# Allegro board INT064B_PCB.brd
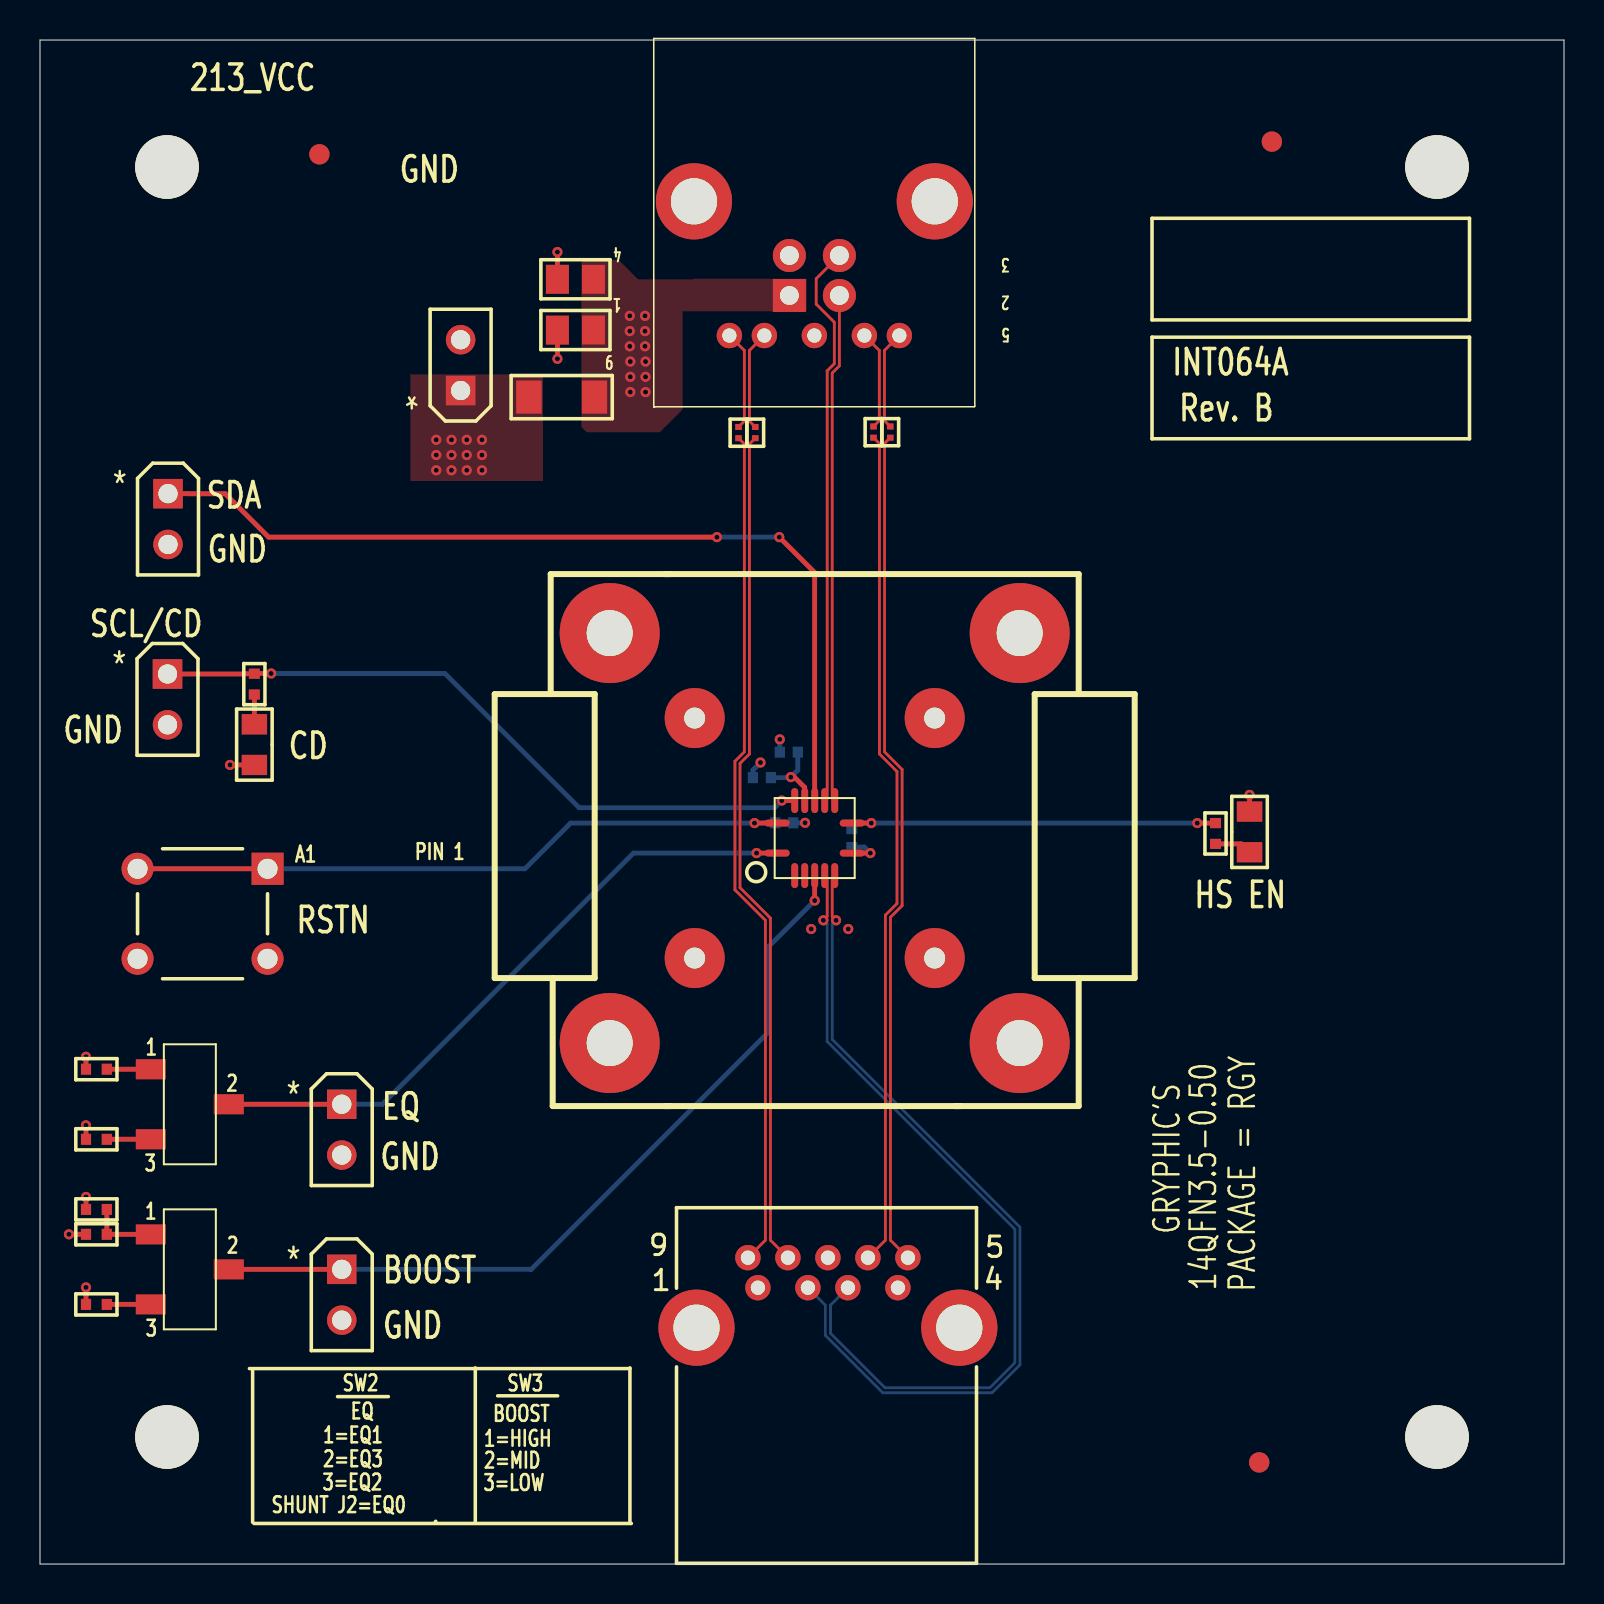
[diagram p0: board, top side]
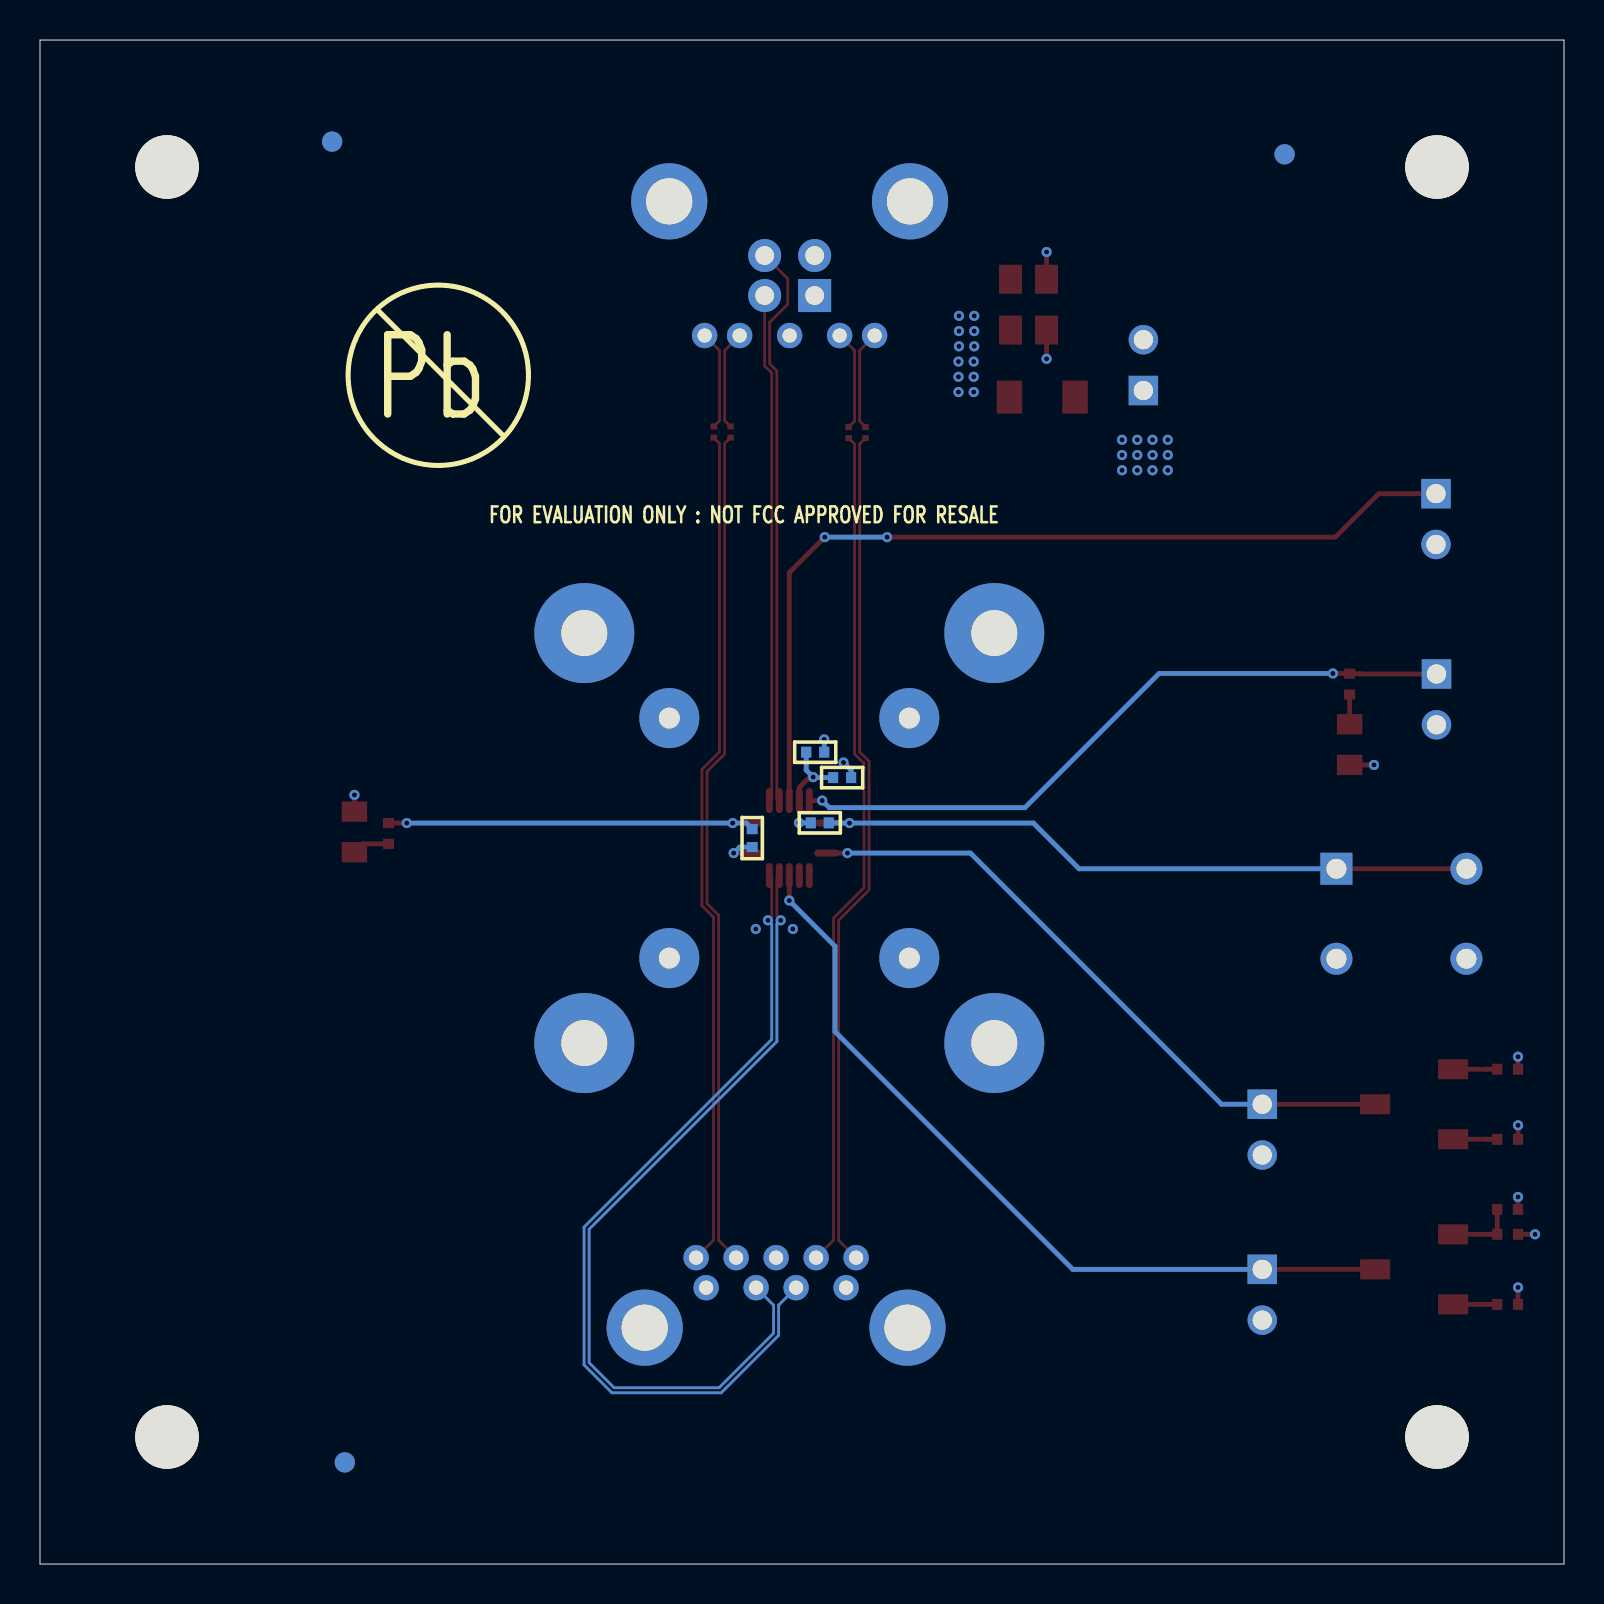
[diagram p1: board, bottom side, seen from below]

Outline 76.2 x 76.2 mm; copper layers: TOP, L2_GND, L3_PWR, BOTTOM. Coordinates in mm from the lower left corner of the outline.
Outline path: 0,76.2 76.2,76.2 76.2,0 0,0 0,76.2

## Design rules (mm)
net group DIFFPAIR0: nets D1M D1P
net group DIFFPAIR1: nets D2M D2P
net group DIFFPAIR2: nets N00734 N00738
net group DIFFPAIR3: nets SS_RXN SS_RXP
net group DIFFPAIR4: nets N00742 N00746
net group DIFFPAIR5: nets SS_TXN SS_TXP

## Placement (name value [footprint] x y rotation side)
C1  0.1uF  [C0402]  40.59 36.3 270 bottom
C2  0.1uF  [C0402]  37.21 37.06 0 bottom
C3  10uF  [C0805]  26.77 64.24 180 top
C4  1uF  [C0805]  26.77 61.7 180 top
C5  1uF  [C0402]  37.44 40.59 180 bottom
C6  0.1uF  [C0402]  36.09 39.32 180 bottom
D1  LED  [0805]  10.72 40.97 90 top
D2  LED  [0805]  60.48 36.6 270 top
J1  HDR2X1 M .1  [HDR_THVT_1X2_100]  21.03 58.67 180 top
J2  HDR2X1 M .1  [HDR_THVT_1X2_100]  15.09 22.99 0 top
J3  HDR2X1 M .1  [HDR_THVT_1X2_100]  6.4 53.52 0 top
J4  HDR2X1 M .1  [HDR_THVT_1X2_100]  6.38 44.5 0 top
J5  HDR2X1 M .1  [HDR_THVT_1X2_100]  15.09 14.73 0 top
NOREF  -  []  -3.81 -69.85 0 top
NOREF#2  -  []  0 76.2 0 top
NOREF#3  -  []  76.2 0 90 top
NOREF#4  -  [unnamed#2]  6.35 69.85 0 top
NOREF#5  -  []  73.51 21.26 90 top
NOREF#6  -  [unnamed#2]  13.97 70.48 0 top
NOREF#7  -  [unnamed#2]  61.59 71.12 0 top
NOREF#8  -  [unnamed#2]  60.96 5.08 0 top
NOREF#9  -  [unnamed#2]  6.35 6.35 0 top
NOREF#10  -  []  88.9 38.1 0 top
NOREF#11  -  [unnamed#2]  69.85 69.85 0 top
NOREF#12  -  [unnamed#2]  69.85 6.35 0 top
NOREF#13  -  []  0 0 0 top
NOREF#14  -  []  10.39 60.66 180 bottom
NOREF#15  -  [unnamed#2]  61.59 71.12 180 bottom
NOREF#16  -  []  56.29 59.44 180 bottom
NOREF#17  -  [unnamed#2]  60.96 5.08 180 bottom
NOREF#18  -  [unnamed#2]  13.97 70.48 180 bottom
P1  USB3.0 Type B Receptacle  [USB3_TYPEB_AK4AA009]  37.47 63.42 180 top
P2  USB3 Type A Receptacle  [USB3_TYPEA]  39.4 15.32 0 top
R1  0  [R0201]  34.92 56.57 270 top
R2  0  [R0201]  35.76 56.57 270 top
R3  0  [R0201]  41.68 56.59 270 top
R4  0  [R0201]  42.51 56.59 270 top
R5  0  [R1206]  26.09 58.34 180 top
R6  1.7K  [R0402]  2.82 24.74 0 top
R7  3.8K  [R0402]  2.82 21.23 0 top
R8  75  [R0402]  10.72 43.99 90 top
R9  75  [R0402]  58.78 36.53 270 top
R10  15K  [R0402]  2.82 16.48 0 top
R11  12K  [R0402]  2.82 12.98 0 top
R12  30K  [R0402]  2.82 17.73 0 top
SW1  Switch - Push Button  [SW_THVT_EVQPAX04]  8.13 32.51 270 top
SW2  Switch CJS-1201  [CJS-1200B]  7.49 22.99 0 top
SW3  Switch CJS-1201  [CJS-1200B]  7.49 14.73 0 top
U1  TUSB213  [RGY_NOPOWERPAD_SOCKET]  38.73 36.3 0 top

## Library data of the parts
C1 C2 C5 C6 = cc0402
C3 C4 = cc0805
D1 D2 = d0805 Green
J1-J5 = HDR2X1 M .1
P1 = USB 3.0 Type B Receptacle
P2 = USB 3.0 Type A Receptacle
R1-R4 = r0201
R5 = r1206
R6-R12 = r0402
SW1 = Switch - Push Button_0
SW2 SW3 = Switch CJS-1201
U1 = TUSB213RGY_2

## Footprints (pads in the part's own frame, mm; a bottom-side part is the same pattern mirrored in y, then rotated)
0805
  rect 1.016x1.27 smd: 1(-1.016,0) 2(1.016,0)
C0402
  rect 0.51x0.55 smd: 1(-0.45,0) 2(0.45,0)
C0805
  rect 1.15x1.45 smd: 1(-0.9,0) 2(0.9,0)
CJS-1200B
  rect 1.5x1 smd: 1(-1.95,1.75) 2(1.95,0) 3(-1.95,-1.75)
HDR_THVT_1X2_100
  rect 1.473x1.473 hole 0.965: 1(0,0)
  round 1.473 hole 0.965: 2(0,-2.54)
R0201
  rect 0.3x0.33 smd: 1(-0.285,0) 2(0.275,0)
R0402
  rect 0.51x0.55 smd: 1(-0.52,0) 2(0.52,0)
R1206
  rect 1.27x1.65 smd: 1(-1.64,0) 2(1.64,0)
RGY_NOPOWERPAD_SOCKET
  round 5 hole 2.3: (-10.25,10.25) (-10.25,-10.25) (10.25,10.25) (10.25,-10.25)
  round 3 hole 1.05 unplated: (-6,6) (-6,-6) (6,6) (6,-6)
  oval 1.25x0.35 smd: 1(-1.875,-0.75) 7(1.875,-0.75) 8(1.875,0.75) 14(-1.875,0.75)
  oval 0.35x1.25 smd: 2(-1,-1.875) 3(-0.5,-1.875) 4(0,-1.875) 5(0.5,-1.875) 6(1,-1.875) 9(1,1.875) 10(0.5,1.875) 11(0,1.875) 12(-0.5,1.875) 13(-1,1.875)
SW_THVT_EVQPAX04
  rect 1.6x1.6 hole 1: A1(-2.25,3.25)
  round 1.6 hole 1: A2(-2.25,-3.25) B1(2.25,3.25) B2(2.25,-3.25)
unnamed#2
  round 3.175 hole 3.175 unplated: (0,0)
USB3_TYPEA
  round 1.27 hole 0.711: 1(-3.5,-1.5) 2(-1,-1.5) 3(1,-1.5) 4(3.5,-1.5) 5(4,0) 6(2,0) 7(0,0) 8(-2,0) 9(-4,0)
  round 3.81 hole 2.311: 10(-6.57,-3.5) 11(6.57,-3.5)
USB3_TYPEB_AK4AA009
  rect 1.651x1.651 hole 0.94: 1(0,0)
  round 1.651 hole 0.94: 2(-2.5,0) 3(-2.5,-2) 4(0,-2)
  round 1.27 hole 0.711: 5(-5.5,2) 6(-3.75,2) 7(-1.25,2) 8(1.25,2) 9(3,2)
  round 3.81 hole 2.311: 10(-7.27,-4.71) 11(4.77,-4.71)

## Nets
GND: C1.2 C2.2 C3.2 C4.2 C5.2 C6.2 D1.1 D2.1 J1.2 J2.2 J3.2 J4.2 J5.2 P1.4(GND) P1.7(GND_DRAIN) P1.10(SHIELD1) P1.11(SHIELD2) P2.4(GND) P2.7(GND_DRAIN) P2.10(SHIELD1) P2.11(SHIELD2) R6.1 R7.1 R11.1 R12.1 SW1.B1 SW1.B2 U1.7(GND)
VBUS: C3.1 C4.1 P1.1(VBUS) P2.1(VBUS) R5.1
213_VCC: C5.1 C6.1 J1.1 R5.2 R10.1 U1.12(VCC)
BOOST: J5.1 SW3.2 U1.4(BOOST/ENA_HS)
D1M: P1.2(USB2_DM) U1.9(D1M)
D1P: P1.3(USB2_DP) U1.10(D1P)
D2M: P2.2(USB2_DM) U1.6(D2M)
D2P: P2.3(USB2_DP) U1.5(D2P)
EQ: J2.1 SW2.2 U1.1(EQ)
RSTN: C2.1 SW1.A1 SW1.A2 U1.14(RSTN)
SCL/CD: J4.1 R8.2 U1.13(SCL/CD)
SDA: J3.1 U1.11(SDA)
SS_RXN: P2.8(SS_TX_N) R2.2
SS_RXP: P2.9(SS_TX_P) R1.2
SS_TXN: P2.5(SS_RX_N) R4.2
SS_TXP: P2.6(SS_RX_P) R3.2
N00734: P1.9(SS_RX_P) R1.1
N00738: P1.8(SS_RX_N) R2.1
N00742: P1.6(SS_TX_P) R3.1
N00746: P1.5(SS_TX_N) R4.1
N01473: C1.1 R9.1 U1.8(VREG)
N16640698: R6.2 SW2.1
N16640702: R7.2 SW2.3
N16641600: D2.2 R9.2
N16641940: D1.2 R8.1
N16642584: R10.2 R12.2 SW3.1
N16642766: R11.2 SW3.3

Pads without a net: U1 2 3

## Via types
v1: diameter 0.508, hole 0.254, TOP to BOTTOM, 51 vias

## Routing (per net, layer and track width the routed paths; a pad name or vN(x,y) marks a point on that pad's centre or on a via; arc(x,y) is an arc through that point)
GND: length 83.2
  TOP w0.241: C3.2 v1(25.87,65.6) ; R11.1 v1(2.3,13.83) ; C4.2 v1(25.87,60.26) ; D2.1 v1(60.48,38.46) ; R12.1 v1(2.3,18.35) ; U1.7 v1(41.52,35.55) ; R6.1 v1(2.3,25.36) ; R7.1 v1(2.3,21.93) ; D1.1 v1(9.5,39.95)
  L2_GND w0.241: P2.10 32.83,13.9 ; P2.10 32.83,9.73 ; P2.10 30.74,11.82 ; P2.10 34.91,11.82 ; J5.2 15.09,13.11 ; J5.2 16,12.19 ; J5.2 15.09,11.28 ; J5.2 14.17,12.19 ; 42.66,68.13 P1.10 ; P1.10 44.74,66.05 ; P1.10 44.74,70.22 ; P1.10 46.82,68.13 ; 4.88,29.28 SW1.B2 ; SW1.B2 4.88,31.24 ; SW1.B2 3.9,30.26 ; SW1.B2 5.86,30.26 ; P1.4 38.47,65.42 ; P1.4 36.47,65.42 ; P1.4 37.47,66.43 ; 39.4,14.5 P2.7 ; P2.7 38.58,15.32 ; P2.7 39.4,16.13 ; P2.7 40.21,15.32 ; J3.2 7.32,50.98 ; J3.2 6.4,51.89 ; J3.2 6.4,50.06 ; J3.2 5.49,50.98 ; J4.2 6.38,42.88 ; J4.2 6.38,41.05 ; J4.2 7.29,41.96 ; J4.2 5.46,41.96 ; 20.12,61.21 J1.2 ; J1.2 21.95,61.21 ; J1.2 21.03,62.13 ; J1.2 21.03,60.3 ; 37.91,61.42 P1.7 ; P1.7 39.53,61.42 ; P1.7 38.72,60.61 ; P1.7 38.72,62.24 ; 14.17,20.45 J2.2 ; J2.2 16,20.45 ; J2.2 15.09,21.36 ; J2.2 15.09,19.53 ; 10.4,30.26 SW1.B1 ; SW1.B1 12.36,30.26 ; SW1.B1 11.38,29.28 ; SW1.B1 11.38,31.24 ; 32.7,66.05 P1.11 ; P1.11 32.7,70.22 ; P1.11 30.62,68.13 ; P1.11 34.78,68.13 ; 45.97,9.73 P2.11 ; P2.11 48.05,11.82 ; P2.11 45.97,13.9 ; P2.11 43.88,11.82 ; P2.4 43.71,13.82 ; P2.4 42.9,13 ; P2.4 42.08,13.82
  BOTTOM w0.241: C5.2 v1(36.99,41.23) ; v1(41.52,35.55) 41.22,35.85 C1.2 ; v1(36.02,40.07) 35.64,39.69 C6.2 ; C2.2 v1(38.25,37.06)
  vias: v1(38.56,31.75) v1(40.41,31.75)
VBUS: length 2.4
  L3_PWR w0.241: 35.9,13 P2.1 ; P2.1 36.71,13.82 ; P2.1 35.08,13.82
  vias: v1(29.49,62.41) v1(29.49,61.65) v1(29.49,60.88) v1(29.51,60.12) v1(29.51,59.36) v1(29.51,58.6) v1(30.25,62.41) v1(30.25,61.65) v1(30.25,60.88) v1(30.28,60.12) v1(30.28,59.36) v1(30.28,58.6)
213_VCC: length 4.8
  TOP w0.241: R10.1 v1(1.45,16.48) ; v1(37.54,39.34) 37.72,39.34 38.23,38.83 U1.12
  BOTTOM w0.241: C6.1 37.52,39.32 v1(37.54,39.34) 37.89,39.69 C5.1
  vias: v1(19.81,56.21) v1(19.81,55.45) v1(19.81,54.69) v1(20.57,56.21) v1(20.57,55.45) v1(20.57,54.69) v1(21.34,56.21) v1(21.34,55.45) v1(21.34,54.69) v1(22.1,56.21) v1(22.1,55.45) v1(22.1,54.69)
BOOST: length 40.7
  TOP w0.241: U1.4 v1(38.73,33.17) ; SW3.2 J5.1
  BOTTOM w0.241: J5.1 24.56,14.73 36.45,26.62 36.45,30.89 v1(38.73,33.17)
D1M: length 25.5
  TOP w0.14: P1.2 39.97,59.91 39.61,59.55 39.61,38.29 U1.9
D1P: length 28.3
  TOP w0.14: P1.3 38.81,64.27 38.81,62.99 39.72,62.09 39.72,60.01 39.36,59.66 39.36,38.29 U1.10
D2M: length 42.8
  TOP w0.14: U1.6 39.61,34.3 39.61,32.38 v1(39.8,32.18)
  BOTTOM w0.14: v1(39.8,32.18) 39.61,31.99 39.61,26.23 49,16.84 49,9.96 47.6,8.56 42.14,8.56 39.27,11.43 39.27,12.94 P2.2
D2P: length 42
  TOP w0.14: U1.5 39.36,34.3 39.36,32.38 v1(39.17,32.18)
  BOTTOM w0.14: v1(39.17,32.18) 39.36,31.99 39.36,26.12 48.74,16.74 48.74,10.06 47.49,8.81 42.24,8.81 39.52,11.54 39.52,12.94 P2.3
EQ: length 32.6
  TOP w0.241: U1.1 v1(35.83,35.55) ; SW2.2 J2.1
  BOTTOM w0.241: J2.1 17.12,22.99 29.68,35.55 v1(35.83,35.55)
RSTN: length 34
  TOP w0.241: SW1.A1 SW1.A2 ; U1.14 v1(35.73,37.05)
  BOTTOM w0.241: C2.1 36.26,37.06 36.25,37.05 v1(35.73,37.05) 26.53,37.05 24.25,34.76 SW1.A1
SCL/CD: length 34.3
  TOP w0.241: v1(11.56,44.53) 10.73,44.53 R8.2 10.2,44.51 10.18,44.5 J4.1 ; U1.13 v1(37.09,38.17)
  BOTTOM w0.241: v1(37.09,38.17) 36.73,37.82 26.95,37.82 20.24,44.53 v1(11.56,44.53)
SDA: length 45.4
  TOP w0.241: v1(36.96,51.34) 38.73,49.57 U1.11 ; v1(33.85,51.34) 11.43,51.34 9.26,53.51 7.39,53.51 7.39,53.52 J3.1
  BOTTOM w0.241: v1(36.96,51.34) v1(33.85,51.34)
SS_RXN: length 42.3
  TOP w0.14: P2.8 36.52,16.19 36.52,32.29 35,33.81 35,40.03 35.47,40.5 35.47,56 R2.2
SS_RXP: length 42.3
  TOP w0.14: R1.2 35.22,56 35.22,40.61 34.75,40.14 34.75,33.71 36.27,32.18 36.27,16.19 P2.9
SS_TXN: length 42.1
  TOP w0.14: R4.2 42.23,56.03 42.23,40.61 43.1,39.73 43.1,32.92 42.52,32.34 42.52,16.19 P2.5
SS_TXP: length 42.1
  TOP w0.14: P2.6 42.27,16.19 42.27,32.44 42.85,33.02 42.85,39.62 41.97,40.5 41.97,56.02 R3.2
N00734: length 5
  TOP w0.14: R1.1 35.22,57.14 35.22,60.68 P1.9
N00738: length 5
  TOP w0.14: P1.8 35.47,60.68 35.47,57.14 R2.1
N00742: length 5
  TOP w0.14: R3.1 41.97,57.17 41.97,60.68 P1.6
N00746: length 5
  TOP w0.14: R4.1 42.22,57.17 42.22,60.68 P1.5
N01473: length 19.3
  TOP w0.241: v1(57.86,37.05) R9.1 ; U1.8 v1(41.57,37.05)
  BOTTOM w0.241: C1.1 40.89,37.05 v1(41.57,37.05) v1(57.86,37.05)
N16640698: length 2.2
  TOP w0.241: SW2.1 3.84,24.74 3.84,24.74 R6.2
N16640702: length 2.2
  TOP w0.241: R7.2 3.84,21.23 3.84,21.24 SW2.3
N16641600: length 1.9
  TOP w0.241: R9.2 60.06,36.01 D2.2
N16641940: length 1.5
  TOP w0.241: R8.1 D1.2
N16642584: length 3.4
  TOP w0.241: R12.2 R10.2 3.84,16.48 3.84,16.48 SW3.1
N16642766: length 2.2
  TOP w0.241: R11.2 3.84,12.98 3.84,12.98 SW3.3

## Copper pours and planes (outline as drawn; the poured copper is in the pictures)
GND on L2_GND: 0.51,0.51 0.51,75.69 75.69,75.69 75.69,0.51
VBUS on TOP: 38.33,62.56 38.33,64.26 32.66,64.26 32.64,64.24 29.9,64.24 28.93,65.2 27.18,65.2 27.08,65.1 27.08,56.85 27.33,56.59 30.99,56.59 32.13,57.73 32.13,62.64 38.25,62.64
VBUS on L3_PWR: 0.51,0.51 0.51,14.17 5.82,14.17 6.32,14.68 6.32,46.28 21.66,46.28 29.44,38.51 38.21,38.51 38.38,38.68 38.38,42.19 26.42,54.16 26.42,75.69 75.69,75.69 75.69,0.51
213_VCC on TOP: 18.52,59.49 18.52,54.15 25.15,54.15 25.15,59.49
213_VCC on L3_PWR: 0.51,14.68 0.51,75.69 25.91,75.69 25.91,53.95 37.87,41.98 37.87,39.01 29.65,39.01 21.87,46.79 5.82,46.79 5.82,14.89 5.61,14.68

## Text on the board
BOTTOM: LAYER 4 - BOTTOM SIDE
Board Geometry/Soldermask Bottom: SOLDERMASK BOTTOM
Package Geometry/Pastemask Bottom: PASTEMASK BOTTOM
Ref Des/Silkscreen Bottom: FOR EVALUATION ONLY : NOT FCC APPROVED FOR RESALE | SILKSCREEN BOTTOM
TOP: LAYER 1 - TOP SIDE
Board Geometry/Soldermask Top: SOLDERMASK TOP
Package Geometry/Pastemask Top: PASTEMASK TOP
Ref Des/Silkscreen Top: 3 | 1 | 2 | SHUNT J2=EQ0 | 3=EQ2 | 1=EQ1 | 2=EQ3 | SW2 | EQ | 3=LOW | 1=HIGH | 2=MID | BOOST | SW3 | GND | SCL/CD | 213_VCC | SDA | CD | RSTN | INT064A | Rev. B | HS EN | SILKSCREEN TOP
L2_GND: LAYER 2 - GND PLANE
L3_PWR: LAYER 3 - PWR PLANE
XSECTION_CHART: * AIR 0 MIL | * SOLDERMASK-0.8MIL 0.8 MIL | L1: COPPER_1/2OZ_PLATED 1.4 MIL | * FILL_0.150 5.91 MIL | L2: COPPER_1.0OZ 1.4 MIL | * CORE_1.10 43.31 MIL | L3: COPPER_1.0OZ 1.4 MIL | L4: COPPER_1/2OZ_PLATED 1.4 MIL | DESIGN CROSS SECTION CHART | ___________________________ | TOTAL THICKNESS 62.33 MIL | 1-4
DIMENSION: FABRICATION DRAWING | CAD ORIGIN
User.6: LAYER 1 | LAYER 2 | LAYER 3 | LAYER 4 | LAYER | NO. | TABLE 1: | TOP | L2_GND | L3_PWR | BOTTOM | NAME | DIFFIRENTIAL PAIR | IMPEDANCE (OHMS) | 90  +/- 10% | DIFF TRACE | WIDTH | 0.0055" | SPACING | 0.0045" | SINGLE ENDED | 50 +/- 10% | TRACE WIDTH | 0.0095" | REFERENCE | SPECIAL FAB NOTES: | PLACE DRILL CHART HERE: | 1:FAB SHOP MUST FOLLOW THE SOLDER MASK REVIEW LAYERS. | 2: | MIN. ANNULAR RING 2 MIL EXTERNAL PER IPC-6012C CLASS 2 | REGISTRATION TOLERANCES: METAL +/- X MIL,HOLES +/- X MIL | IMPEDANCE CONTROL: | BOARD SIZE (REFER ALSO ARRAY/PANEL PROFILING INFORMATION) | MIXED DIELECTRIC: | LAMINATE MATERIAL: | THICKNESS: | TOLERANCE: | COPPER THICKNESS (FINISHED): | BOARD FINISH: | NUMBER OF LAYERS: | MIN. TRACK WIDTH: | MIN. CLEARANCE  : | MIN. VIA PAD/DRILL: | THIEVING ALLOWED: | X | OUTER: | INNER SIGNAL: | INNER PLANE: | OTHER: | SILKSCREEN: | SOLDERMASK: (PER IPC-6011,6012) | BOARD SURFACE TREATMENT: | ADDITIONAL REQUIREMENTS: | VENDOR MARKING: | SILKSCREEN COLOR: | SOLDERMASK COLOR: | THROUGH-HOLE VIA TREATMENT: | VIA FILL USING NON-CONDUCTIVE EPOXY: | FOR WIRE BONDING: | VENDOR DATE CODE,UL,LOGO: | FR-4 HIGH Tg | 0.062" +/-10% | IPC-6012C TYPE 3 CLASS 2 | OTHER +/- | MICRO-SECTION | CERTIFICATES OF COMPLIANCE | NICKEL/GOLD (ENIG) | IMMERSION TIN | HARD GOLD | IN AN OPEN AREA | 1/4 OZ. | OPEN | NO | 4 | 5.5 MIL | 4.5 MIL | 20/10 MIL | NONE | DESIGN INFORMATION | ROGERS 4350B | 0.093" +/-10% | YES | TDR REPORTS/COUPONS | WHITE | GREEN | SOFT GOLD | TENTED | 1/2 OZ. | BOW & TWIST: | ORGANIC (OSP) | OTHER | WHERE INDICATED (SEE DRAWING) | YES - SEE TABLE 1 | ETCH | IDENTIFIER: | BLUE | RoHS | 1.0 OZ. | SILKSCREEN | PER SUPPLIED ARTWORK | ALL x MIL VIAS | ELECTRICAL TEST | UL 94V-0 | HASL | 2.0 OZ. | BREAK-AWAY | ENEPIG | FIGURE | B | G | SIZE | 91.0 | 90.55 | 39.37 | 38.0 | 37.0 | 28.0 | 10.0 | 125.0 | 41.34 | DRILL CHART: TOP to BOTTOM | ALL UNITS ARE IN MILS | TOLERANCE | +3.0/-3.0 | +3.94/-0.0 | +2.0/-2.0 | +3.15/-41.34 | PLATED | NON-PLATED | QTY | 10 | 14 | 48
